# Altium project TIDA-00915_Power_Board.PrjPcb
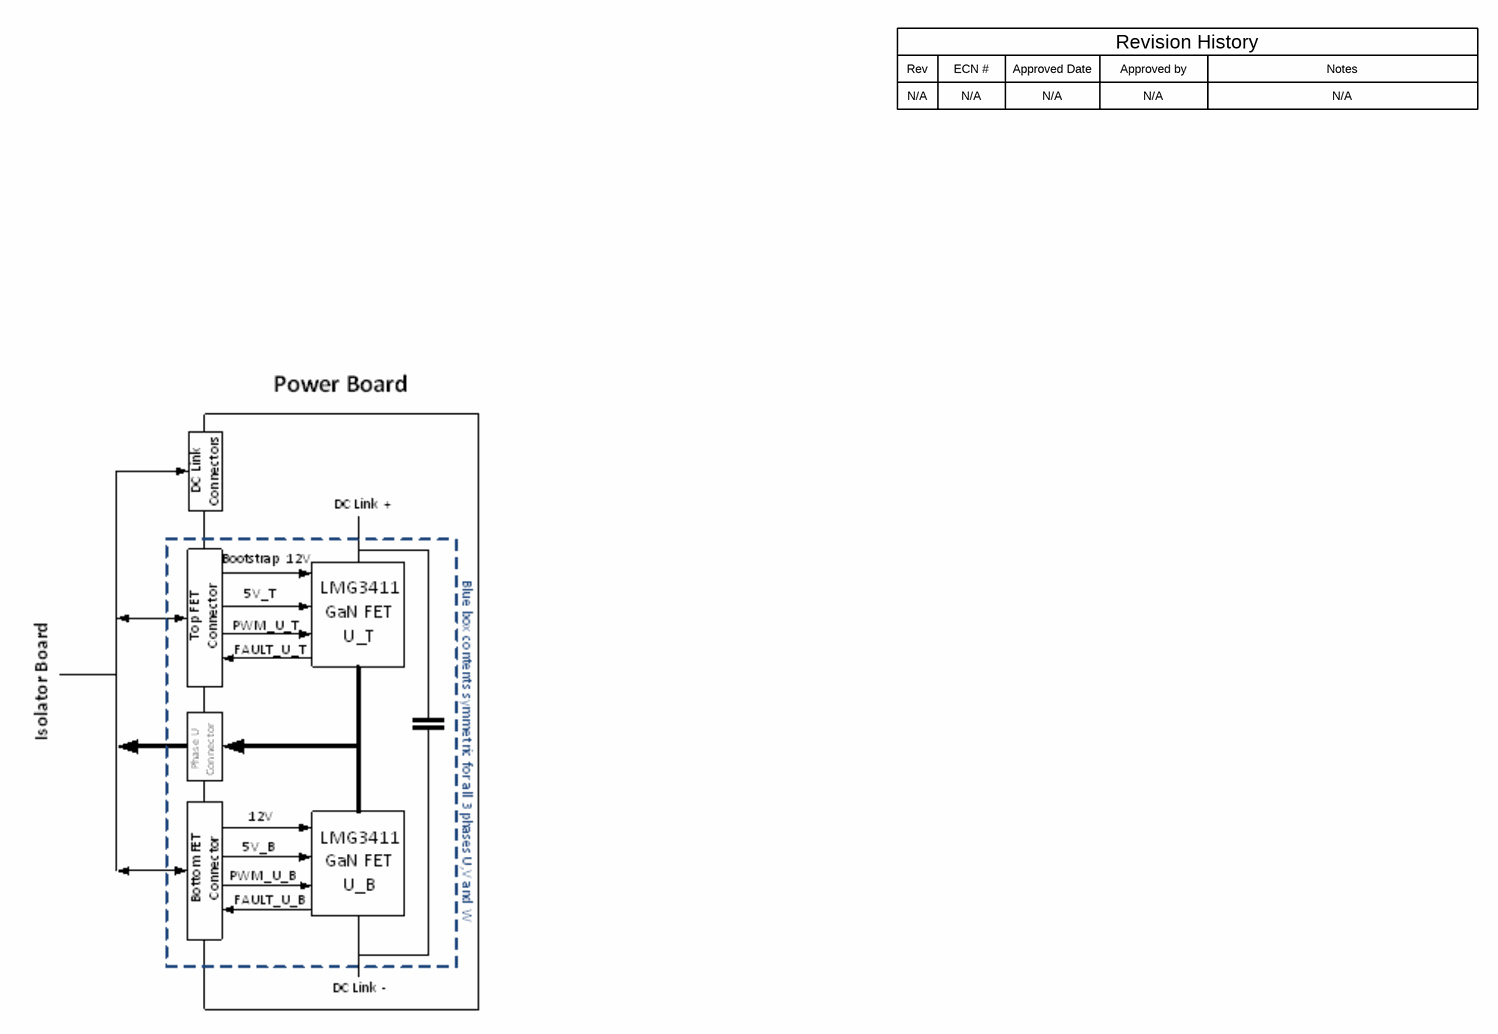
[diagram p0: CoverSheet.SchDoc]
TID: 00915; TechSupport: http://www.ti.com/support; SCH_Rev: E1; PRJ_Title: TIDA-00915_Power_Board; PRJ_Number: TIDA-00915_Power_Board; PRJ_Customer: Public Release; PCB_Rev: E1; CopyrightYear: 2019
5 sheets, 95 parts. Net scope: global (net labels, ports and power ports of the same name join across sheets).
Board file: TIDA-00915_Power_Board.PcbDoc
Sheets:
  CoverSheet.SchDoc
  EVM_Hardware.SchDoc
  Phase_U.SchDoc
  Phase_V.SchDoc
  Phase_W.SchDoc

## Sheet CoverSheet.SchDoc
size 431 x 279 mm; Date: Not shown in title block; ApprovedBy: Not shown in title block; CheckedBy: Not shown in title block; Author: Not shown in title block; CompanyName: Not shown in title block; Engineer: Not shown in title block; Organization: Not shown in title block; Address1: Not shown in title block; Address2: Not shown in title block; Address3: Not shown in title block; Address4: Not shown in title block; DocumentNumber: 1; Revision: Use project parameter SCH_Rev; SheetNumber: 1; SheetTotal: 3; PageSetup: Record=PageOptions¦CenterHorizontal=True¦CenterVertical=True¦PrintScale=1.00¦XCorrection=1.00¦YCorrection=1.00¦PrintKind=0¦BorderSize=5000000¦LeftOffset=0¦BottomOffset=0¦Orientation=2¦PaperLength=1000¦PaperWidth=1000¦Scale=100¦PaperSource=15¦PrintQuality=600¦MediaType=1¦DitherType=10¦PaperKind=Letter¦PrintScaleMode=1

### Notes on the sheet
- Rev
- N/A
- ECN #
- Approved Date
- Approved by
- Revision History
- Notes

## Sheet EVM_Hardware.SchDoc
size 431 x 279 mm; Date: Not shown in title block; ApprovedBy: Not shown in title block; CheckedBy: Not shown in title block; Author: Not shown in title block; CompanyName: Not shown in title block; Engineer: Not shown in title block; Organization: Not shown in title block; Address1: Not shown in title block; Address2: Not shown in title block; Address3: Not shown in title block; Address4: Not shown in title block; DocumentNumber: 1; Revision: Use project parameter SCH_Rev; SheetNumber: 3; SheetTotal: 3; PageSetup: Record=PageOptions¦CenterHorizontal=True¦CenterVertical=True¦PrintScale=1.00¦XCorrection=1.00¦YCorrection=1.00¦PrintKind=0¦BorderSize=5000000¦LeftOffset=0¦BottomOffset=0¦Orientation=2¦PaperLength=1000¦PaperWidth=1000¦Scale=100¦PaperSource=15¦PrintQuality=600¦MediaType=1¦DitherType=10¦PaperKind=Letter¦PrintScaleMode=1
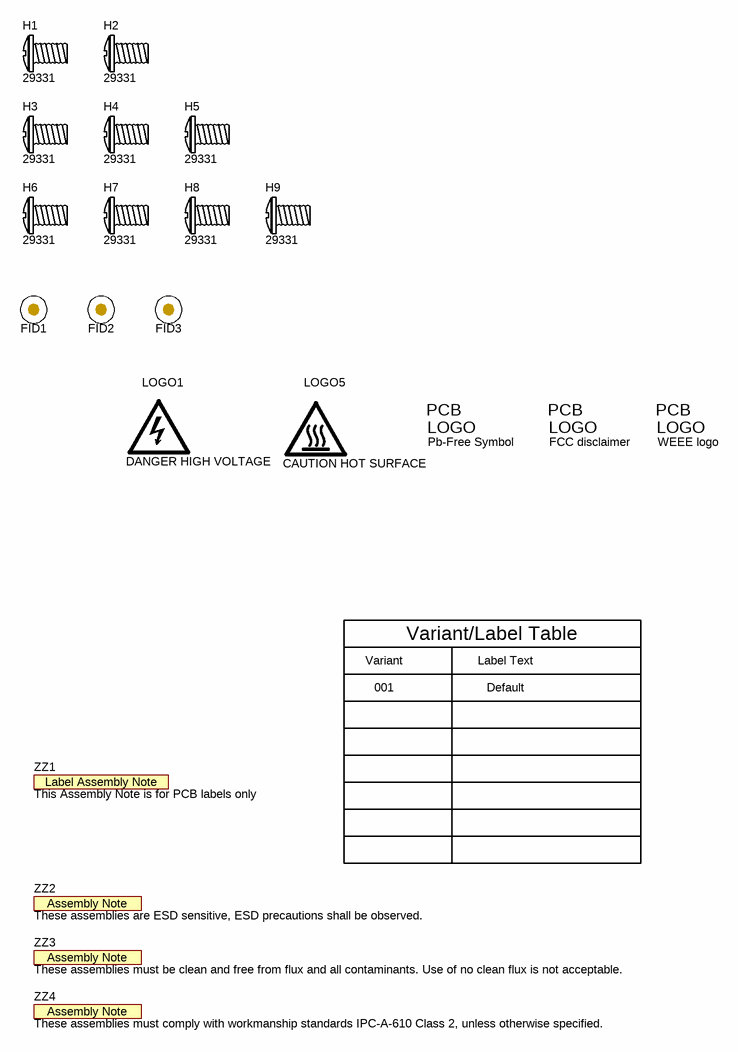
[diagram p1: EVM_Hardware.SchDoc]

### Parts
FID1  Fiducial  [Fiducial10-20]  (value not drawn)
FID2  Fiducial  [Fiducial10-20]  (value not drawn)
FID3  Fiducial  [Fiducial10-20]  (value not drawn)
H1  29331  [Keystone_29331]
H2  29331  [Keystone_29331]
H3  29331  [Keystone_29331]
H4  29331  [Keystone_29331]
H5  29331  [Keystone_29331]
H6  29331  [Keystone_29331]
H7  29331  [Keystone_29331]
H8  29331  [Keystone_29331]
H9  29331  [Keystone_29331]
LOGO1  DANGER HIGH VOLTAGE  [IEC_HighVoltage_Small]  (no BOM)
Logo2  Pb-Free Symbol  [Pb-Free_Overlay_Small]  (no BOM)
Logo3  FCC disclaimer  [FCC_disclaimer]  (no BOM)
Logo4  WEEE logo  [WEEE_Minimum]  (no BOM)
LOGO5  CAUTION HOT SURFACE  [IEC_HotSurface_Small]  (no BOM)
ZZ1  This Assembly Note is for PCB labels only  [AssemblyNoteLabel]  (no BOM)
ZZ2  These assemblies are ESD sensitive, ESD precautions shall be observed.  [AssemblyNote]  (no BOM)
ZZ3  These assemblies must be clean and free from flux and all contaminants. Use of no clean flux is not acceptable.  [AssemblyNote]  (no BOM)
ZZ4  These assemblies must comply with workmanship standards IPC-A-610 Class 2, unless otherwise specified.  [AssemblyNote]  (no BOM)

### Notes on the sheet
- Variant
- Variant/Label Table
- Label Text
- 001
- Default

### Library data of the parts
FID1-FID3 = CMP-0077181-1: Fiducial mark.  There is nothing to buy or mount.
H1-H9 = CMP-0086212-3: MACH SCREW FLAT SLOTTED #4-40; Manufacturer: Keystone
LOGO1 = CMP-0074835-1: IEC 61010-1 High Voltage Warning; Library Reference: IEC_HighVoltage; SymbolCreator: a0412235
Logo2 = CMP-0074839-1: SymbolCreator: a0412235; Library Reference: Logo
Logo3 = CMP-0074847-1: FCC_disclaimer; Library Reference: Logo
Logo4 = CMP-0074769-1
LOGO5 = CMP-0074837-1: IEC 61010-1 Hot Surface Warning; Library Reference: IEC_HotSurface; SymbolCreator: a0412235
ZZ1 = CMP-0003616-3
ZZ2 = CMP-0077236-1
ZZ3 = CMP-0077237-1
ZZ4 = CMP-0077238-1

## Sheet Phase_U.SchDoc
size 431 x 279 mm; Date: Not shown in title block; ApprovedBy: Not shown in title block; CheckedBy: Not shown in title block; Author: Not shown in title block; CompanyName: Not shown in title block; Engineer: Not shown in title block; Organization: Not shown in title block; Address1: Not shown in title block; Address2: Not shown in title block; Address3: Not shown in title block; Address4: Not shown in title block; DocumentNumber: 1; Revision: Use project parameter SCH_Rev; SheetNumber: 2; SheetTotal: 3; PageSetup: Record=PageOptions¦CenterHorizontal=True¦CenterVertical=True¦PrintScale=1.00¦XCorrection=1.00¦YCorrection=1.00¦PrintKind=0¦BorderSize=5000000¦LeftOffset=0¦BottomOffset=0¦Orientation=2¦PaperLength=1000¦PaperWidth=1000¦Scale=100¦PaperSource=15¦PrintQuality=600¦MediaType=1¦DitherType=10¦PaperKind=Letter¦PrintScaleMode=1
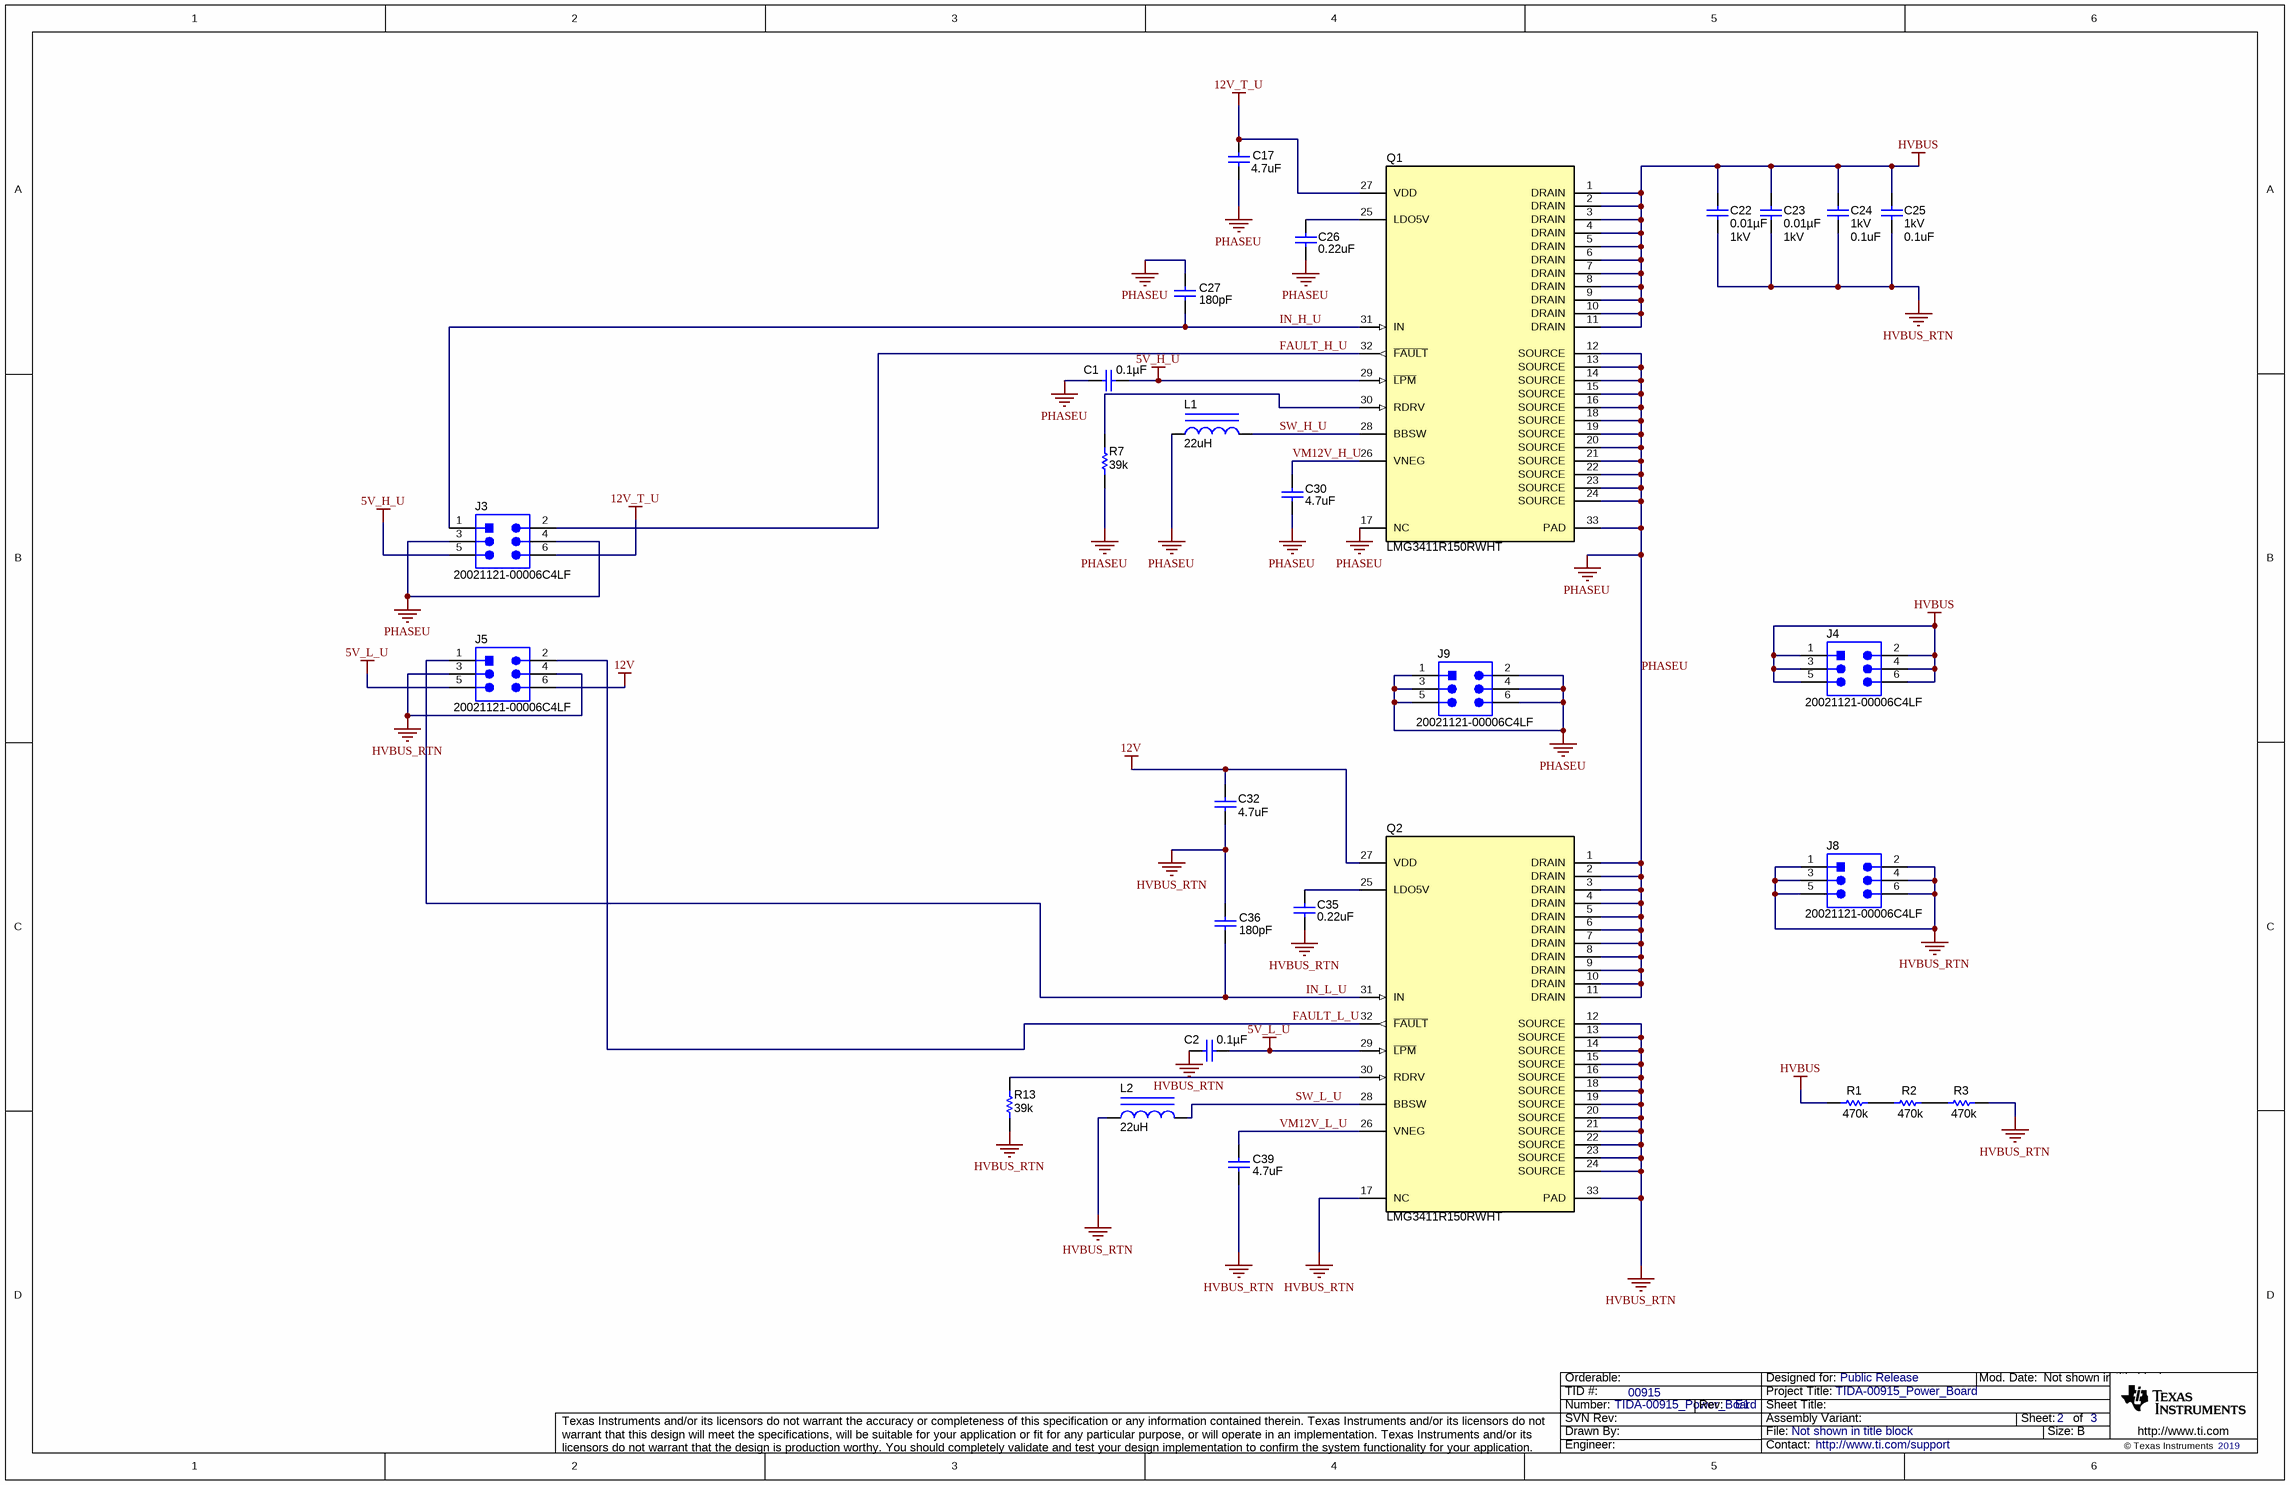
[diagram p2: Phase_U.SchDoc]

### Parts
C1  ValueDisplayed: 0.1µF  [0402]  (hidden comment: CGA2B3X7R1E104K050BB)
C2  ValueDisplayed: 0.1µF  [0402]  (hidden comment: CGA2B3X7R1E104K050BB)
C17  ValueDisplayed: 4.7uF  [0805_HV]  (hidden comment: C2012X7R1V475K125AC)
C22  ValueDisplayed: 0.01µF  VDC_V: 1kV  [1206]  (hidden comment: C1206X103KDRAC7800)
C23  ValueDisplayed: 0.01µF  VDC_V: 1kV  [1206]  (hidden comment: C1206X103KDRAC7800)
C24  VDC_V: 1kV  ValueDisplayed: 0.1uF  [1812_254]  (hidden comment: C1812V104KDRACTU)
C25  VDC_V: 1kV  ValueDisplayed: 0.1uF  [1812_254]  (hidden comment: C1812V104KDRACTU)
C26  ValueDisplayed: 0.22uF  [0603]  (hidden comment: GCM188R71E224KA55D)
C27  ValueDisplayed: 180pF  [0603]  (hidden comment: 06035A181JAT2A)
C30  ValueDisplayed: 4.7uF  [0805_HV]  (hidden comment: C2012X7R1V475K125AC)
C32  ValueDisplayed: 4.7uF  [0805_HV]  (hidden comment: C2012X7R1V475K125AC)
C35  ValueDisplayed: 0.22uF  [0603]  (hidden comment: GCM188R71E224KA55D)
C36  ValueDisplayed: 180pF  [0603]  (hidden comment: 06035A181JAT2A)
C39  ValueDisplayed: 4.7uF  [0805_HV]  (hidden comment: C2012X7R1V475K125AC)
J3  20021121-00006C4LF  [FCI_20021121-00006x4]
J4  20021121-00006C4LF  [FCI_20021121-00006x4]
J5  20021121-00006C4LF  [FCI_20021121-00006x4]
J8  20021121-00006C4LF  [FCI_20021121-00006x4]
J9  20021121-00006C4LF  [FCI_20021121-00006x4]
L1  ValueDisplayed: 22uH  [1007]  (hidden comment: BRC2518T220K)
L2  ValueDisplayed: 22uH  [1007]  (hidden comment: BRC2518T220K)
Q1  LMG3411R150RWHT  [RWH0032A_NV]
Q2  LMG3411R150RWHT  [RWH0032A_NV]
R1  ValueDisplayed: 470k  [1206]  (hidden comment: CRCW1206470KJNEA)
R2  ValueDisplayed: 470k  [1206]  (hidden comment: CRCW1206470KJNEA)
R3  ValueDisplayed: 470k  [1206]  (hidden comment: CRCW1206470KJNEA)
R7  ValueDisplayed: 39k  [0402]  (hidden comment: CRCW040239K0JNED)
R13  ValueDisplayed: 39k  [0402]  (hidden comment: CRCW040239K0JNED)

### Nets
5V_H_U: C1.1 J3.5 Q1.29(~{LPM})
5V_L_U: C2.1 J5.5 Q2.29(~{LPM})
12V: C32.1 J5.6 Q2.27(VDD)
12V_T_U: C17.1 J3.6 Q1.27(VDD)
HVBUS: C22.1 C23.1 C24.1 C25.1 J4.1 J4.2 J4.3 J4.4 J4.5 J4.6 Q1.1(DRAIN) Q1.2(DRAIN) Q1.3(DRAIN) Q1.4(DRAIN) Q1.5(DRAIN) Q1.6(DRAIN) Q1.7(DRAIN) Q1.8(DRAIN) Q1.9(DRAIN) Q1.10(DRAIN) Q1.11(DRAIN) R1.1
HVBUS_RTN: C2.2 C22.2 C23.2 C24.2 C25.2 C32.2 C35.2 C36.1 C39.2 J5.3 J5.4 J8.1 J8.2 J8.3 J8.4 J8.5 J8.6 L2.1 Q2.12(SOURCE) Q2.13(SOURCE) Q2.14(SOURCE) Q2.15(SOURCE) Q2.16(SOURCE) Q2.17(NC) Q2.18(SOURCE) Q2.19(SOURCE) Q2.20(SOURCE) Q2.21(SOURCE) Q2.22(SOURCE) Q2.23(SOURCE) Q2.24(SOURCE) Q2.33(PAD) R3.2 R13.1
PHASEU: C1.2 C17.2 C26.2 C27.1 C30.2 J3.3 J3.4 J9.1 J9.2 J9.3 J9.4 J9.5 J9.6 L1.1 Q1.12(SOURCE) Q1.13(SOURCE) Q1.14(SOURCE) Q1.15(SOURCE) Q1.16(SOURCE) Q1.17(NC) Q1.18(SOURCE) Q1.19(SOURCE) Q1.20(SOURCE) Q1.21(SOURCE) Q1.22(SOURCE) Q1.23(SOURCE) Q1.24(SOURCE) Q1.33(PAD) Q2.1(DRAIN) Q2.2(DRAIN) Q2.3(DRAIN) Q2.4(DRAIN) Q2.5(DRAIN) Q2.6(DRAIN) Q2.7(DRAIN) Q2.8(DRAIN) Q2.9(DRAIN) Q2.10(DRAIN) Q2.11(DRAIN) R7.1
FAULT_H_U: J3.2 Q1.32(~{FAULT})
FAULT_L_U: J5.2 Q2.32(~{FAULT})
IN_H_U: C27.2 J3.1 Q1.31(IN)
IN_L_U: C36.2 J5.1 Q2.31(IN)
SW_H_U: L1.2 Q1.28(BBSW)
SW_L_U: L2.2 Q2.28(BBSW)
VM12V_H_U: C30.1 Q1.26(VNEG)
VM12V_L_U: C39.1 Q2.26(VNEG)
NetC26_1: C26.1 Q1.25(LDO5V)
NetC35_1: C35.1 Q2.25(LDO5V)
NetQ1_30: Q1.30(RDRV) R7.2
NetQ2_30: Q2.30(RDRV) R13.2
NetR1_2: R1.2 R2.1
NetR2_2: R2.2 R3.1

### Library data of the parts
C1 C2 = CMP-0080610-1: CAP, CERM, 0.1 µF, 25 V,+/- 10%, X7R, AEC-Q200 Grade 1, 0402; Manufacturer: TDK; TaMin_C: -55°C; Polarized: N; SizeAreaWB_mm2: 3; U/M: EA; Value: 0.1uF; TaMax_C: 125°C; SizeZ_mm: 0.6; SizeX_mm: 1; SizeY_mm: 0.5; Value2: 25V; CompType: Capacitor; AEC Qualified: Y; Cap_F: 100nF; AEC Category: Q200
C17 C30 C32 C39 = CMP-0007885-2: CAP, CERM, 4.7 uF, 35 V, +/- 10%, X7R, 0805; Manufacturer: TDK; TaMin_C: -55°C; ESR_ohm: 2.346m; Polarized: N; SizeAreaWB_mm2: 6.75; Value1: 0.002346 ohm; U/M: EA; Value: 4.7uF; TaMax_C: 125°C; SizeZ_mm: 1.45; SizeX_mm: 2; SizeY_mm: 1.25; Cap_Case: 0805; Value2: 35V; SizeArea_mm2: 2.5; CompType: Capacitor; Cap_F: 4.7µF; IRMS_A: 4.26021A; AEC Category: Q200
C22 C23 = CMP-0085177-1: CAP, CERM, 0.01 µF, 1000 V,+/- 10%, X7R, 1206; Manufacturer: Kemet; SizeZ_mm: 1.35; SizeArea_mm2: 5.12; AEC Category: Q200; Cap_F: 10nF; U/M: EA; SizeY_mm: 1.6; SizeX_mm: 3.2; Value2: 1000V; TaMax_C: 125°C; Polarized: N; SizeAreaWB_mm2: 10.92; Value: 0.01uF; TaMin_C: -55°C
C24 C25 = CMP-0009324-2: CAP, CERM, 0.1 uF, 1000 V, +/- 10%, X7R, 1812; Manufacturer: Kemet; TaMin_C: -55°C; Polarized: N; SizeAreaWB_mm2: 23.1; Value1: Unknown; U/M: EA; Value: 0.1uF; TaMax_C: 125°C; SizeZ_mm: 2.54; SizeX_mm: 4.5; SizeY_mm: 3.2; Cap_Case: 1812; Value2: 1000V; SizeArea_mm2: 14.4; Cap_F: 100nF; AEC Category: Q200
C26 C35 = CMP-0007140-4: CAP, CERM, 0.22 uF, 25 V, +/- 10%, X7R, AEC-Q200 Grade 1, 0603; Manufacturer: MuRata; TaMin_C: -55°C; Polarized: N; SizeAreaWB_mm2: 4.68; Value1: Unknown; U/M: EA; Value: 0.22uF; TaMax_C: 125°C; SizeZ_mm: 1; SizeX_mm: 1.6; SizeY_mm: 0.8; Value2: 25V; SizeArea_mm2: 1.28; CompType: Capacitor; AEC Qualified: Y; Cap_F: 220nF; AEC Category: Q200
C27 C36 = CMP-0006770-4: CAP, CERM, 180 pF, 50 V, +/- 5%, C0G/NP0, 0603; Manufacturer: AVX; TaMin_C: -55°C; ESR_ohm: 0.09; Polarized: N; SizeAreaWB_mm2: 4.68; Value1: 0.09 ohm; U/M: EA; Value: 180pF; TaMax_C: 125°C; SizeZ_mm: 1; SizeX_mm: 1.6; SizeY_mm: 0.8; Value2: 50V; SizeArea_mm2: 1.28; CompType: Capacitor; AEC Category: Q200
J3-J5 J8 J9 = CMP-0065020-2: Header, 1.27 mm, 3x2, Au, SMT; Manufacturer: FCI; System: Connector
L1 L2 = CMP-0060002-2: Inductor, Wirewound, 22 uH, 0.49 A, 0.56 ohm, SMD; Manufacturer: Taiyo Yuden; Isat: 0.64A @ 30% inductance drop; Irms: 0.49A @ 40C rise; Green_Lifecycle: Active; SizeAreaWB_mm2: 9.8; DCR_ohm: 5.6d; Green_REACh: Passed; Value: 22uH; Imax_A: 4.9dA; SizeZ_mm: 2; SizeX_mm: 2.5; SizeY_mm: 1.8; Value2: 0.49A; SizeArea_mm2: 4.5; Ind_H: 22µH; AEC Qualified: N; AEC Category: Q200
Q1 Q2 = CMP-0086312-1: 600-V 150mohm GaN With Integrated Driver and Cycle-by-cycle Overcurrent Protection, RWH0032A (VQFN-32), RWH0032A (VQFN-32); Alternate PartNumber: LMG3411R150RWHR; Alternate Manufacturer: Texas Instruments; CompType: IC; SizeZ_mm: 0.9; AEC Qualified: N; SizeAreaWB_mm2: 100; AEC Category: Q200; SizeArea_mm2: 64; SizeY_mm: 8
R1-R3 = CMP-0018684-3: RES, 470 k, 5%, 0.25 W, AEC-Q200 Grade 0, 1206; Manufacturer: Vishay-Dale; Power_W: 250mW; TempCo: 200 ppm/C; Value: 470k; EIA_Code: E24; SizeX_mm: 3.2; SizeY_mm: 1.6; SizeZ_mm: 1.35; Value2: 0.25W; SizeArea_mm2: 5.12; CompType: Resistor; AEC Qualified: Y; VDC_V: 200V; AEC Category: Q200; AEC Grade: 0
R7 R13 = CMP-0026915-3: RES, 39 k, 5%, 0.063 W, AEC-Q200 Grade 0, 0402; Manufacturer: Vishay-Dale; Power_W: 63mW; TempCo: 200 ppm/C; Value_Code: 39k0; Value: 39k; EIA_Code: E24; SizeX_mm: 1; SizeY_mm: 0.5; SizeZ_mm: 0.6; Value2: 0.063W; CompType: Resistor; AEC Qualified: Y; VDC_V: 50V; AEC Category: Q200; AEC Grade: 0

## Sheet Phase_V.SchDoc
size 431 x 279 mm; Date: Not shown in title block; ApprovedBy: Not shown in title block; CheckedBy: Not shown in title block; Author: Not shown in title block; CompanyName: Not shown in title block; Engineer: Not shown in title block; Organization: Not shown in title block; Address1: Not shown in title block; Address2: Not shown in title block; Address3: Not shown in title block; Address4: Not shown in title block; DocumentNumber: 1; Revision: Use project parameter SCH_Rev; SheetNumber: 2; SheetTotal: 3; PageSetup: Record=PageOptions¦CenterHorizontal=True¦CenterVertical=True¦PrintScale=1.00¦XCorrection=1.00¦YCorrection=1.00¦PrintKind=0¦BorderSize=5000000¦LeftOffset=0¦BottomOffset=0¦Orientation=2¦PaperLength=1000¦PaperWidth=1000¦Scale=100¦PaperSource=15¦PrintQuality=600¦MediaType=1¦DitherType=10¦PaperKind=Letter¦PrintScaleMode=1
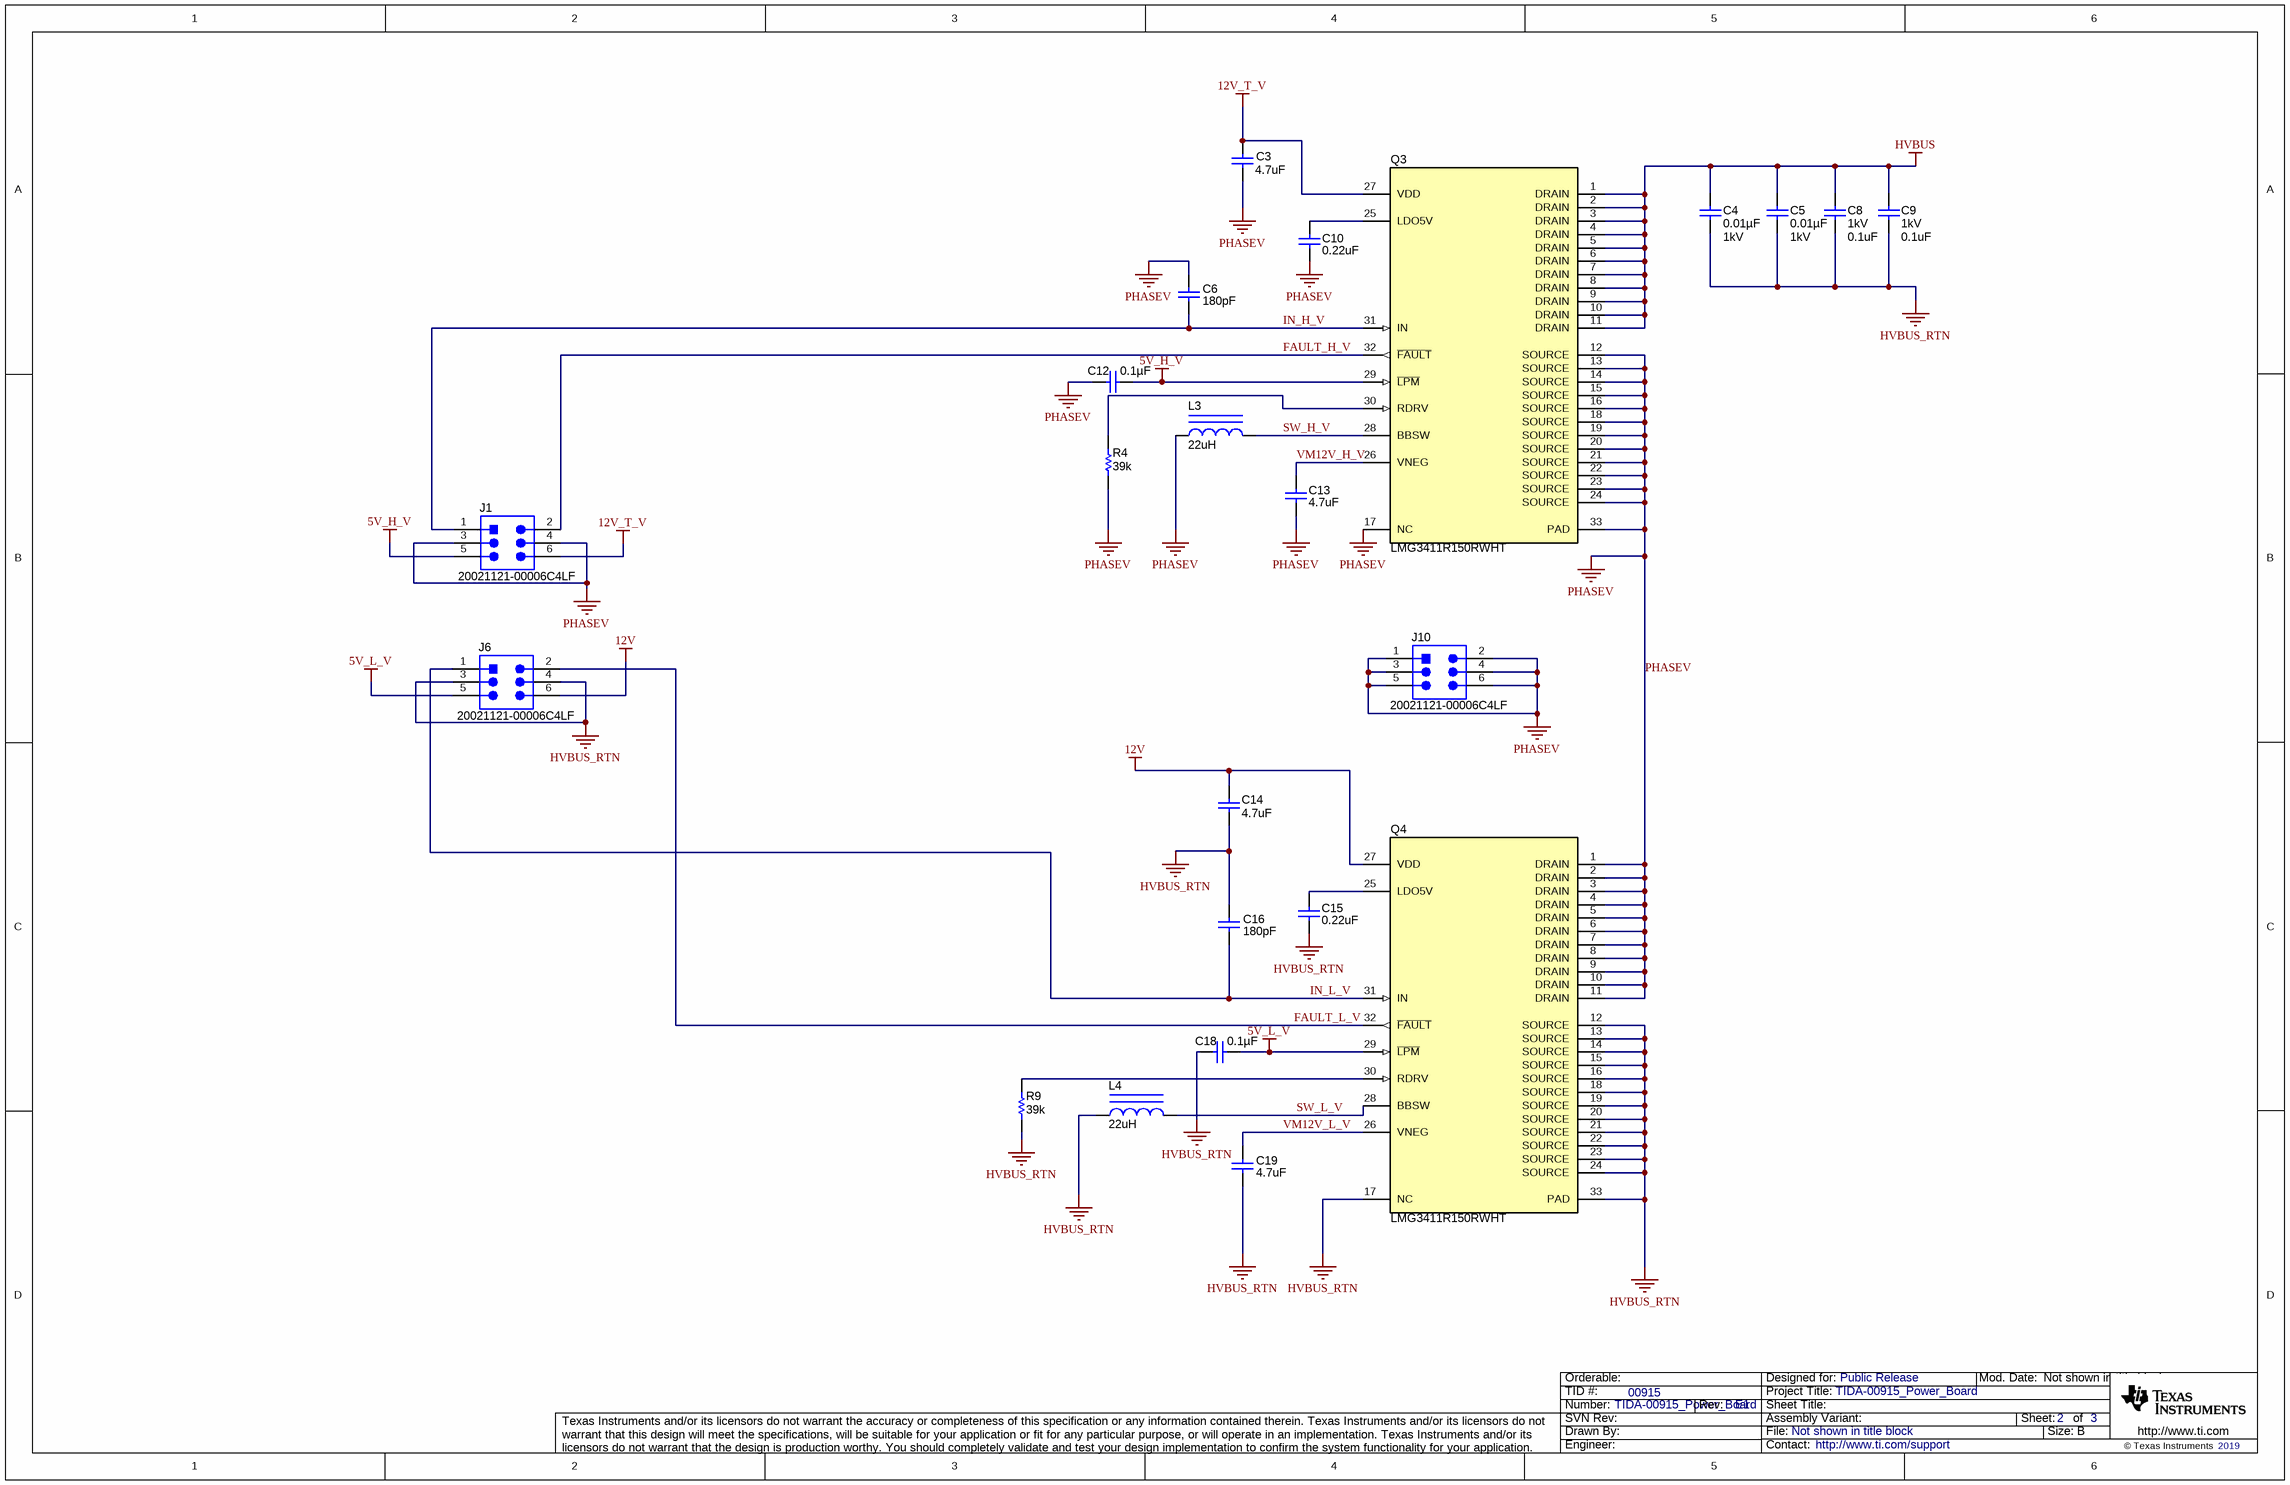
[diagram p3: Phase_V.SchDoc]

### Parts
C3  ValueDisplayed: 4.7uF  [0805_HV]  (hidden comment: C2012X7R1V475K125AC)
C4  ValueDisplayed: 0.01µF  VDC_V: 1kV  [1206]  (hidden comment: C1206X103KDRAC7800)
C5  ValueDisplayed: 0.01µF  VDC_V: 1kV  [1206]  (hidden comment: C1206X103KDRAC7800)
C6  ValueDisplayed: 180pF  [0603]  (hidden comment: 06035A181JAT2A)
C8  VDC_V: 1kV  ValueDisplayed: 0.1uF  [1812_254]  (hidden comment: C1812V104KDRACTU)
C9  VDC_V: 1kV  ValueDisplayed: 0.1uF  [1812_254]  (hidden comment: C1812V104KDRACTU)
C10  ValueDisplayed: 0.22uF  [0603]  (hidden comment: GCM188R71E224KA55D)
C12  ValueDisplayed: 0.1µF  [0402]  (hidden comment: CGA2B3X7R1E104K050BB)
C13  ValueDisplayed: 4.7uF  [0805_HV]  (hidden comment: C2012X7R1V475K125AC)
C14  ValueDisplayed: 4.7uF  [0805_HV]  (hidden comment: C2012X7R1V475K125AC)
C15  ValueDisplayed: 0.22uF  [0603]  (hidden comment: GCM188R71E224KA55D)
C16  ValueDisplayed: 180pF  [0603]  (hidden comment: 06035A181JAT2A)
C18  ValueDisplayed: 0.1µF  [0402]  (hidden comment: CGA2B3X7R1E104K050BB)
C19  ValueDisplayed: 4.7uF  [0805_HV]  (hidden comment: C2012X7R1V475K125AC)
J1  20021121-00006C4LF  [FCI_20021121-00006x4]
J6  20021121-00006C4LF  [FCI_20021121-00006x4]
J10  20021121-00006C4LF  [FCI_20021121-00006x4]
L3  ValueDisplayed: 22uH  [1007]  (hidden comment: BRC2518T220K)
L4  ValueDisplayed: 22uH  [1007]  (hidden comment: BRC2518T220K)
Q3  LMG3411R150RWHT  [RWH0032A_NV]
Q4  LMG3411R150RWHT  [RWH0032A_NV]
R4  ValueDisplayed: 39k  [0402]  (hidden comment: CRCW040239K0JNED)
R9  ValueDisplayed: 39k  [0402]  (hidden comment: CRCW040239K0JNED)

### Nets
5V_H_V: C12.1 J1.5 Q3.29(~{LPM})
5V_L_V: C18.1 J6.5 Q4.29(~{LPM})
12V: C14.1 J6.6 Q4.27(VDD)
12V_T_V: C3.1 J1.6 Q3.27(VDD)
HVBUS: C4.1 C5.1 C8.1 C9.1 Q3.1(DRAIN) Q3.2(DRAIN) Q3.3(DRAIN) Q3.4(DRAIN) Q3.5(DRAIN) Q3.6(DRAIN) Q3.7(DRAIN) Q3.8(DRAIN) Q3.9(DRAIN) Q3.10(DRAIN) Q3.11(DRAIN)
HVBUS_RTN: C4.2 C5.2 C8.2 C9.2 C14.2 C15.2 C16.1 C18.2 C19.2 J6.3 J6.4 L4.1 Q4.12(SOURCE) Q4.13(SOURCE) Q4.14(SOURCE) Q4.15(SOURCE) Q4.16(SOURCE) Q4.17(NC) Q4.18(SOURCE) Q4.19(SOURCE) Q4.20(SOURCE) Q4.21(SOURCE) Q4.22(SOURCE) Q4.23(SOURCE) Q4.24(SOURCE) Q4.33(PAD) R9.1
PHASEV: C3.2 C6.1 C10.2 C12.2 C13.2 J1.3 J1.4 J10.1 J10.2 J10.3 J10.4 J10.5 J10.6 L3.1 Q3.12(SOURCE) Q3.13(SOURCE) Q3.14(SOURCE) Q3.15(SOURCE) Q3.16(SOURCE) Q3.17(NC) Q3.18(SOURCE) Q3.19(SOURCE) Q3.20(SOURCE) Q3.21(SOURCE) Q3.22(SOURCE) Q3.23(SOURCE) Q3.24(SOURCE) Q3.33(PAD) Q4.1(DRAIN) Q4.2(DRAIN) Q4.3(DRAIN) Q4.4(DRAIN) Q4.5(DRAIN) Q4.6(DRAIN) Q4.7(DRAIN) Q4.8(DRAIN) Q4.9(DRAIN) Q4.10(DRAIN) Q4.11(DRAIN) R4.1
FAULT_H_V: J1.2 Q3.32(~{FAULT})
FAULT_L_V: J6.2 Q4.32(~{FAULT})
IN_H_V: C6.2 J1.1 Q3.31(IN)
IN_L_V: C16.2 J6.1 Q4.31(IN)
SW_H_V: L3.2 Q3.28(BBSW)
SW_L_V: L4.2 Q4.28(BBSW)
VM12V_H_V: C13.1 Q3.26(VNEG)
VM12V_L_V: C19.1 Q4.26(VNEG)
NetC10_1: C10.1 Q3.25(LDO5V)
NetC15_1: C15.1 Q4.25(LDO5V)
NetQ3_30: Q3.30(RDRV) R4.2
NetQ4_30: Q4.30(RDRV) R9.2

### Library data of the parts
C3 C13 C14 C19 = CMP-0007885-2: as C17 on sheet Phase_U
C4 C5 = CMP-0085177-1: as C22 on sheet Phase_U
C6 C16 = CMP-0006770-4: as C27 on sheet Phase_U
C8 C9 = CMP-0009324-2: as C24 on sheet Phase_U
C10 C15 = CMP-0007140-4: as C26 on sheet Phase_U
C12 C18 = CMP-0080610-1: as C1 on sheet Phase_U
J1 J6 J10 = CMP-0065020-2: as J3 on sheet Phase_U
L3 L4 = CMP-0060002-2: as L1 on sheet Phase_U
Q3 Q4 = CMP-0086312-1: as Q1 on sheet Phase_U
R4 R9 = CMP-0026915-3: as R7 on sheet Phase_U

## Sheet Phase_W.SchDoc
size 431 x 279 mm; Date: Not shown in title block; ApprovedBy: Not shown in title block; CheckedBy: Not shown in title block; Author: Not shown in title block; CompanyName: Not shown in title block; Engineer: Not shown in title block; Organization: Not shown in title block; Address1: Not shown in title block; Address2: Not shown in title block; Address3: Not shown in title block; Address4: Not shown in title block; DocumentNumber: 1; Revision: Use project parameter SCH_Rev; SheetNumber: 2; SheetTotal: 3; PageSetup: Record=PageOptions¦CenterHorizontal=True¦CenterVertical=True¦PrintScale=1.00¦XCorrection=1.00¦YCorrection=1.00¦PrintKind=0¦BorderSize=5000000¦LeftOffset=0¦BottomOffset=0¦Orientation=2¦PaperLength=1000¦PaperWidth=1000¦Scale=100¦PaperSource=15¦PrintQuality=600¦MediaType=1¦DitherType=10¦PaperKind=Letter¦PrintScaleMode=1
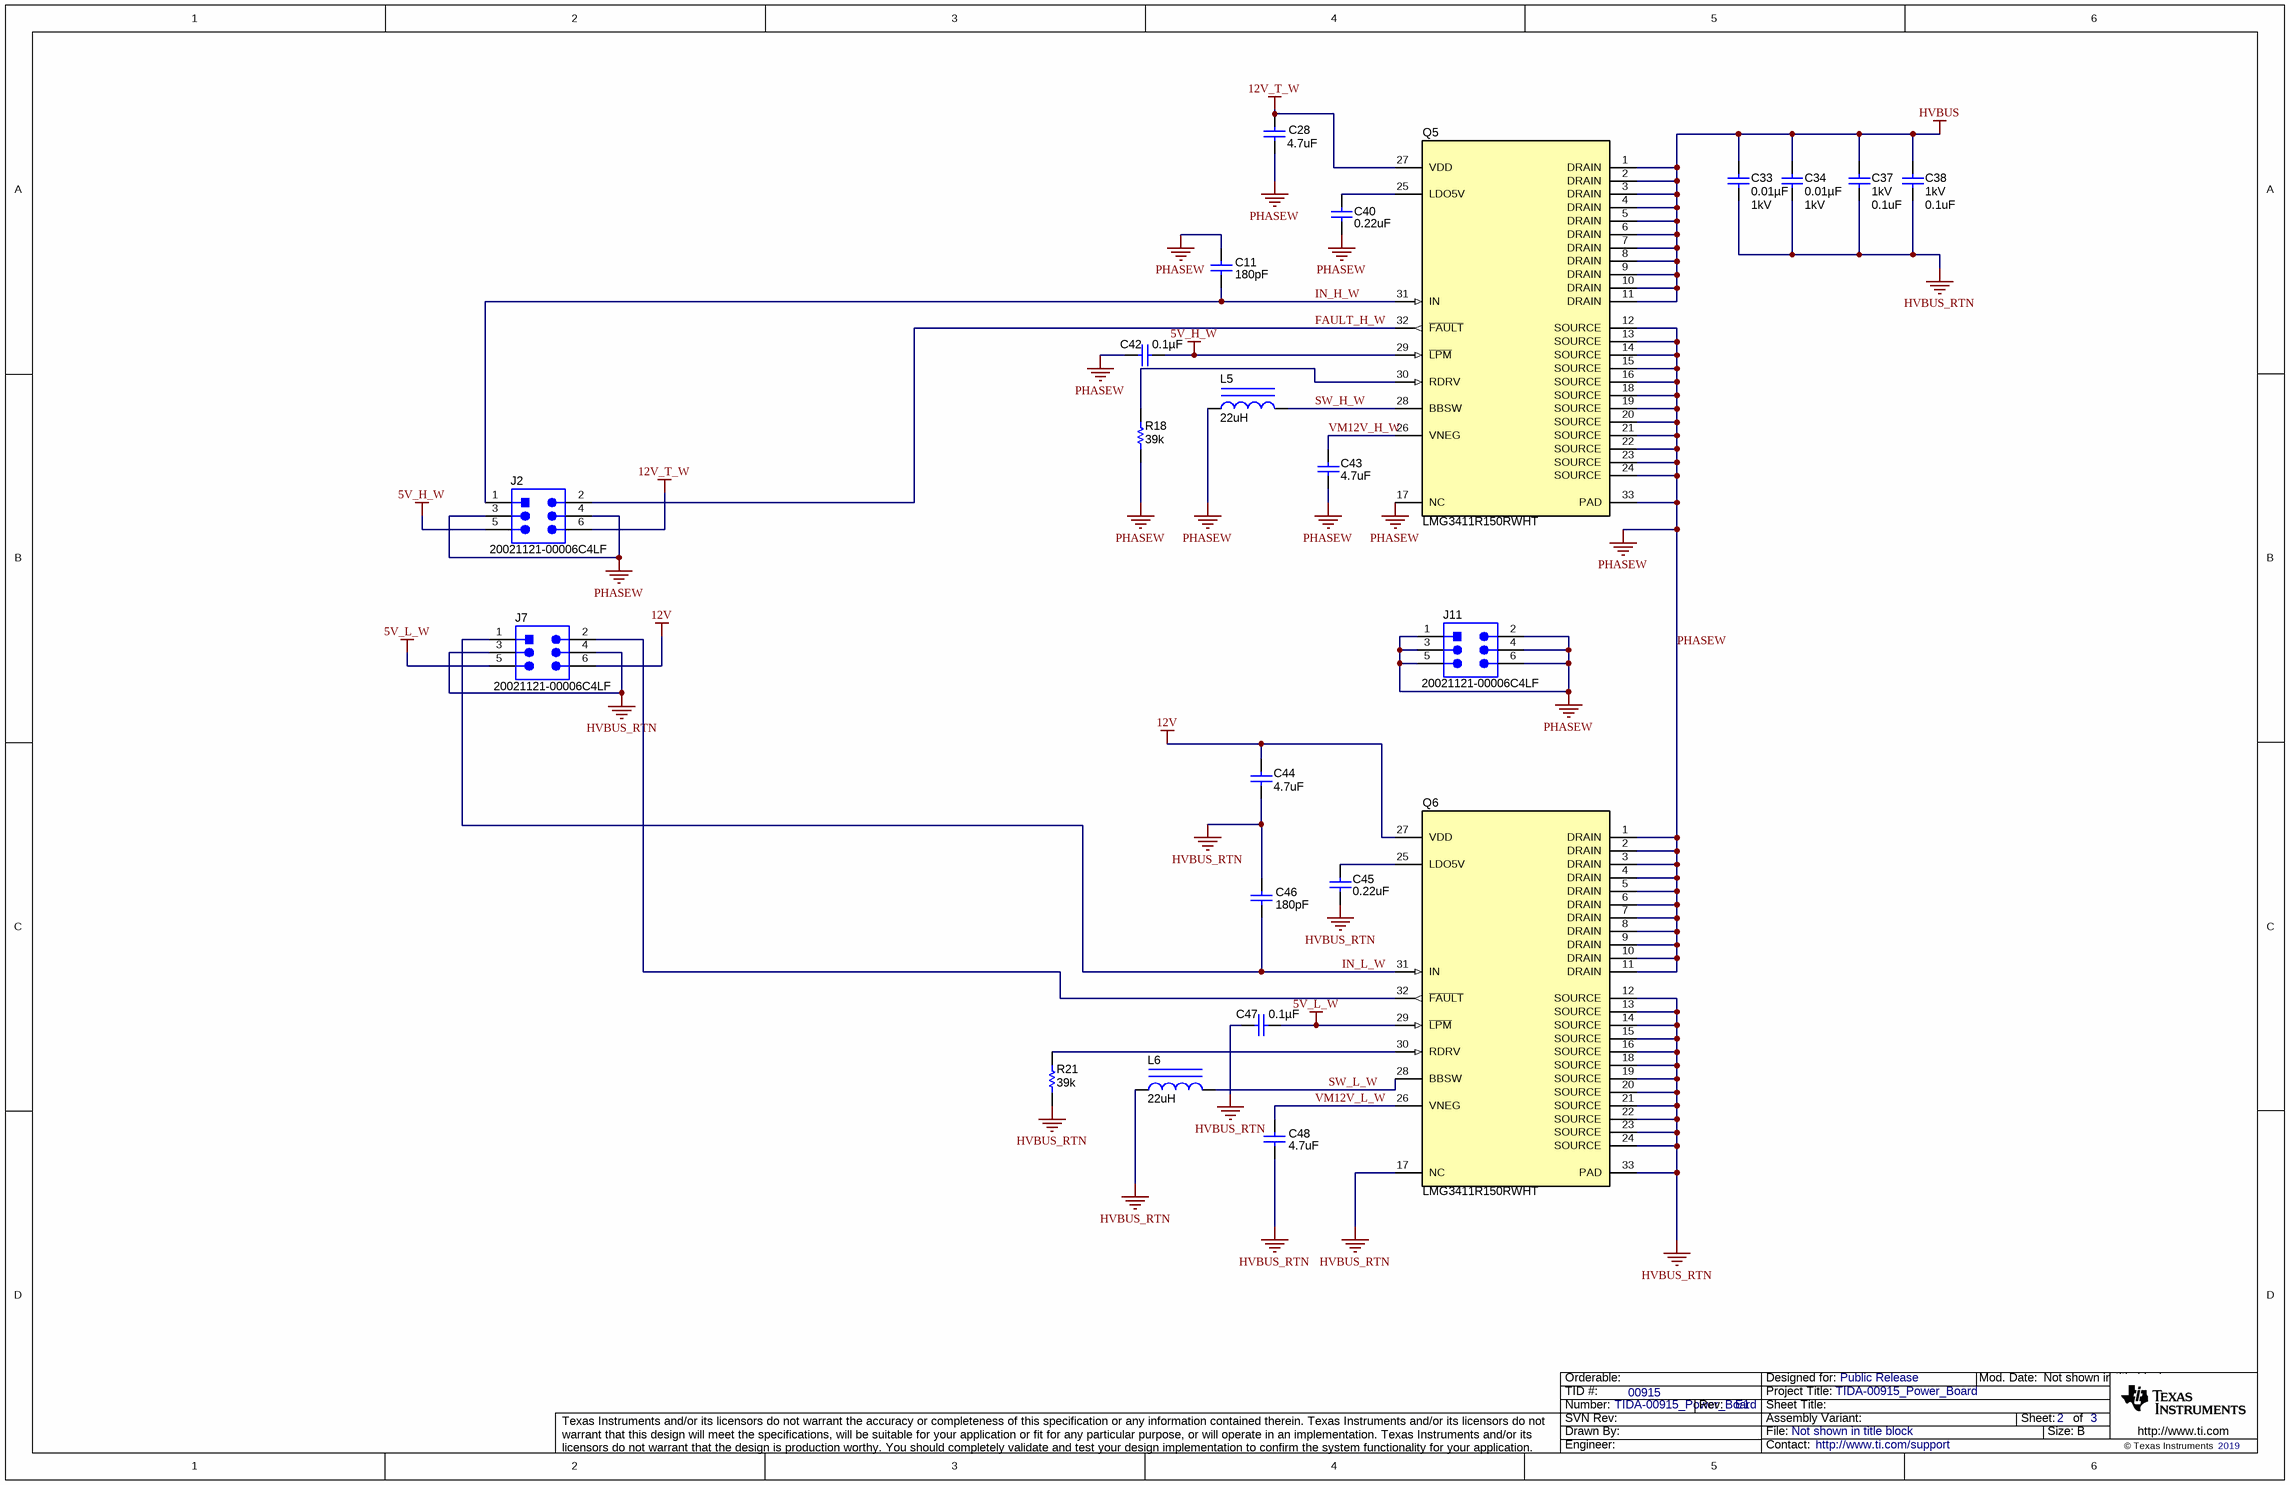
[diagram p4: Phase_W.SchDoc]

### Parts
C11  ValueDisplayed: 180pF  [0603]  (hidden comment: 06035A181JAT2A)
C28  ValueDisplayed: 4.7uF  [0805_HV]  (hidden comment: C2012X7R1V475K125AC)
C33  ValueDisplayed: 0.01µF  VDC_V: 1kV  [1206]  (hidden comment: C1206X103KDRAC7800)
C34  ValueDisplayed: 0.01µF  VDC_V: 1kV  [1206]  (hidden comment: C1206X103KDRAC7800)
C37  VDC_V: 1kV  ValueDisplayed: 0.1uF  [1812_254]  (hidden comment: C1812V104KDRACTU)
C38  VDC_V: 1kV  ValueDisplayed: 0.1uF  [1812_254]  (hidden comment: C1812V104KDRACTU)
C40  ValueDisplayed: 0.22uF  [0603]  (hidden comment: GCM188R71E224KA55D)
C42  ValueDisplayed: 0.1µF  [0402]  (hidden comment: CGA2B3X7R1E104K050BB)
C43  ValueDisplayed: 4.7uF  [0805_HV]  (hidden comment: C2012X7R1V475K125AC)
C44  ValueDisplayed: 4.7uF  [0805_HV]  (hidden comment: C2012X7R1V475K125AC)
C45  ValueDisplayed: 0.22uF  [0603]  (hidden comment: GCM188R71E224KA55D)
C46  ValueDisplayed: 180pF  [0603]  (hidden comment: 06035A181JAT2A)
C47  ValueDisplayed: 0.1µF  [0402]  (hidden comment: CGA2B3X7R1E104K050BB)
C48  ValueDisplayed: 4.7uF  [0805_HV]  (hidden comment: C2012X7R1V475K125AC)
J2  20021121-00006C4LF  [FCI_20021121-00006x4]
J7  20021121-00006C4LF  [FCI_20021121-00006x4]
J11  20021121-00006C4LF  [FCI_20021121-00006x4]
L5  ValueDisplayed: 22uH  [1007]  (hidden comment: BRC2518T220K)
L6  ValueDisplayed: 22uH  [1007]  (hidden comment: BRC2518T220K)
Q5  LMG3411R150RWHT  [RWH0032A_NV]
Q6  LMG3411R150RWHT  [RWH0032A_NV]
R18  ValueDisplayed: 39k  [0402]  (hidden comment: CRCW040239K0JNED)
R21  ValueDisplayed: 39k  [0402]  (hidden comment: CRCW040239K0JNED)

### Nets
5V_H_W: C42.1 J2.5 Q5.29(~{LPM})
5V_L_W: C47.1 J7.5 Q6.29(~{LPM})
12V: C44.1 J7.6 Q6.27(VDD)
12V_T_W: C28.1 J2.6 Q5.27(VDD)
HVBUS: C33.1 C34.1 C37.1 C38.1 Q5.1(DRAIN) Q5.2(DRAIN) Q5.3(DRAIN) Q5.4(DRAIN) Q5.5(DRAIN) Q5.6(DRAIN) Q5.7(DRAIN) Q5.8(DRAIN) Q5.9(DRAIN) Q5.10(DRAIN) Q5.11(DRAIN)
HVBUS_RTN: C33.2 C34.2 C37.2 C38.2 C44.2 C45.2 C46.1 C47.2 C48.2 J7.3 J7.4 L6.1 Q6.12(SOURCE) Q6.13(SOURCE) Q6.14(SOURCE) Q6.15(SOURCE) Q6.16(SOURCE) Q6.17(NC) Q6.18(SOURCE) Q6.19(SOURCE) Q6.20(SOURCE) Q6.21(SOURCE) Q6.22(SOURCE) Q6.23(SOURCE) Q6.24(SOURCE) Q6.33(PAD) R21.1
PHASEW: C11.1 C28.2 C40.2 C42.2 C43.2 J2.3 J2.4 J11.1 J11.2 J11.3 J11.4 J11.5 J11.6 L5.1 Q5.12(SOURCE) Q5.13(SOURCE) Q5.14(SOURCE) Q5.15(SOURCE) Q5.16(SOURCE) Q5.17(NC) Q5.18(SOURCE) Q5.19(SOURCE) Q5.20(SOURCE) Q5.21(SOURCE) Q5.22(SOURCE) Q5.23(SOURCE) Q5.24(SOURCE) Q5.33(PAD) Q6.1(DRAIN) Q6.2(DRAIN) Q6.3(DRAIN) Q6.4(DRAIN) Q6.5(DRAIN) Q6.6(DRAIN) Q6.7(DRAIN) Q6.8(DRAIN) Q6.9(DRAIN) Q6.10(DRAIN) Q6.11(DRAIN) R18.1
FAULT_H_W: J2.2 Q5.32(~{FAULT})
IN_H_W: C11.2 J2.1 Q5.31(IN)
IN_L_W: C46.2 J7.1 Q6.31(IN)
SW_H_W: L5.2 Q5.28(BBSW)
SW_L_W: L6.2 Q6.28(BBSW)
VM12V_H_W: C43.1 Q5.26(VNEG)
VM12V_L_W: C48.1 Q6.26(VNEG)
NetC40_1: C40.1 Q5.25(LDO5V)
NetC45_1: C45.1 Q6.25(LDO5V)
NetJ7_2: J7.2 Q6.32(~{FAULT})
NetQ5_30: Q5.30(RDRV) R18.2
NetQ6_30: Q6.30(RDRV) R21.2

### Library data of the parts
C11 C46 = CMP-0006770-4: as C27 on sheet Phase_U
C28 C43 C44 C48 = CMP-0007885-2: as C17 on sheet Phase_U
C33 C34 = CMP-0085177-1: as C22 on sheet Phase_U
C37 C38 = CMP-0009324-2: as C24 on sheet Phase_U
C40 C45 = CMP-0007140-4: as C26 on sheet Phase_U
C42 C47 = CMP-0080610-1: as C1 on sheet Phase_U
J2 J7 J11 = CMP-0065020-2: as J3 on sheet Phase_U
L5 L6 = CMP-0060002-2: as L1 on sheet Phase_U
Q5 Q6 = CMP-0086312-1: as Q1 on sheet Phase_U
R18 R21 = CMP-0026915-3: as R7 on sheet Phase_U

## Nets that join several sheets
12V: Phase_U (C32.1 J5.6 Q2.27), Phase_V (C14.1 J6.6 Q4.27), Phase_W (C44.1 J7.6 Q6.27)
HVBUS: Phase_U (22 pins), Phase_V (15 pins), Phase_W (15 pins)
HVBUS_RTN: Phase_U (34 pins), Phase_V (27 pins), Phase_W (27 pins)

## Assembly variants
001: not fitted FID1 FID2 FID3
